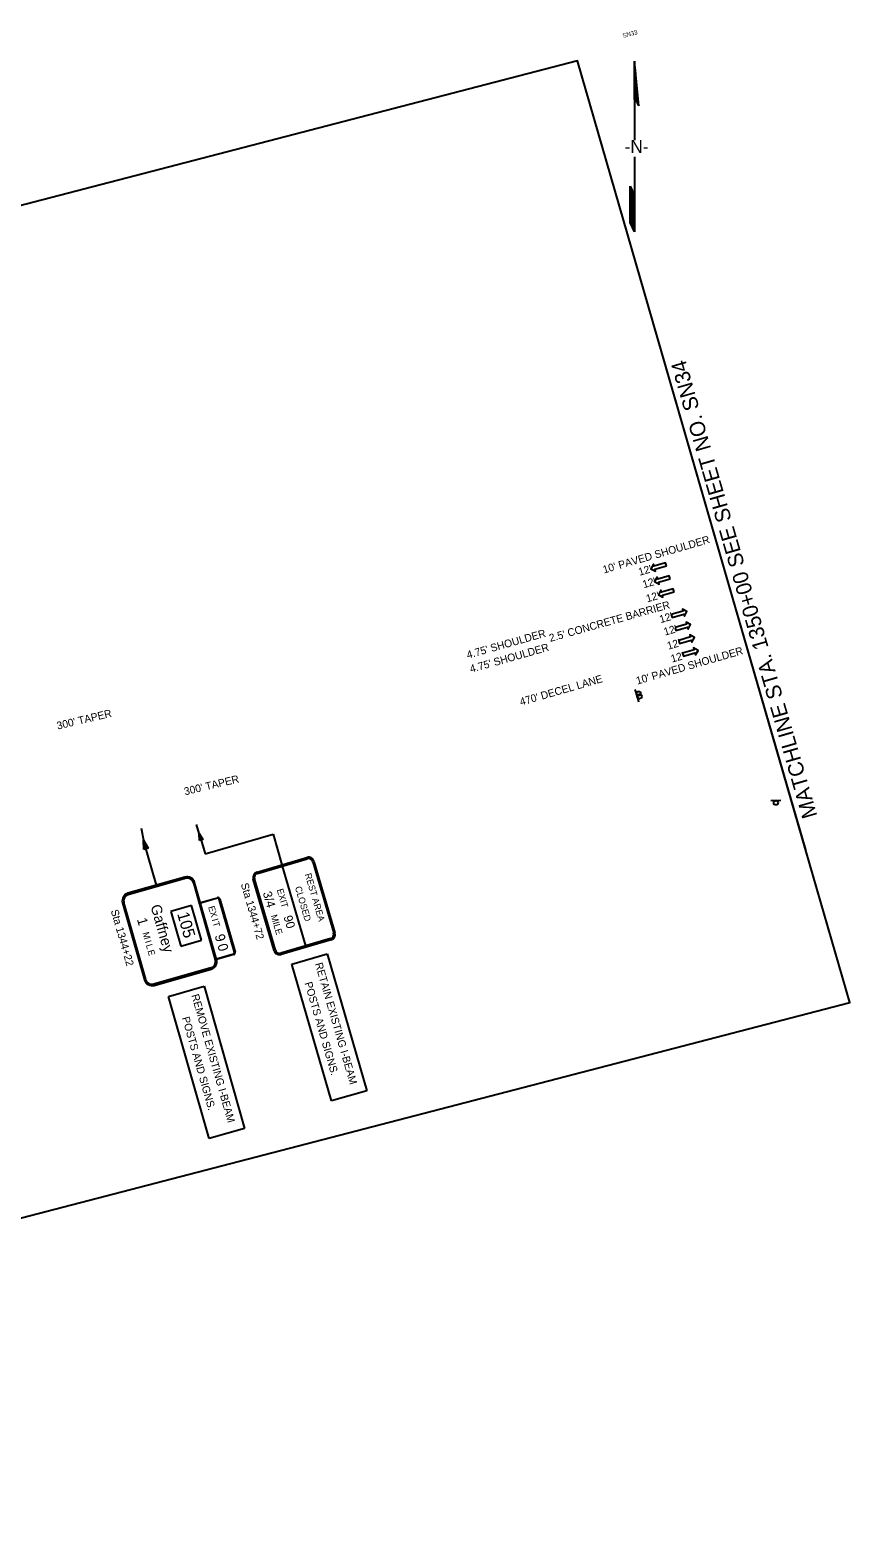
# Model space of a CAD drawing. Extents: x 1782675 to 1784334, y 1180551 to 1181928.
# Drawn here: x 1783586 to 1784334, y 1180551 to 1181928 of the extents above; entities that cross this region are included whole.
import ezdxf

# ---------------------------------------------------------------- set-up
doc = ezdxf.new("R2010")
doc.units = 0
for name, color, linetype in [('RD_HC_Data', 7, 'Continuous'), ('RD_PD_GR', 7, 'Continuous'), ('RD_PD_MedBWall', 7, 'Continuous'), ('RD_PD_PatLn1', 7, 'Continuous'), ('RD_PD_PaveShd', 7, 'Continuous'), ('RD_SHT_MatchLine', 7, 'Continuous'), ('RD_Sketch1', 7, 'Continuous')]:
    doc.layers.add(name, color=color, linetype=linetype)

# ---------------------------------------------------------------- blocks, each defined once
blk = doc.blocks.new('NA5')
at = {"layer": 'RD_Sketch1'}
for p, q in [((47.5, 65.9), (26.8, 37.4)), ((26.8, 30.6), (47.5, 65.9)), ((27.2, 37.5), (14.5, 19.8)), ((28.1, 38.3), (26.8, 30.6)), ((14.5, 19.8), (5.5, 7.2)), ((-3.5, -5.3), (-18.5, -26.3)), ((-18.5, -26.3), (-43.3, -60.9)), ((-30.6, -36.2), (-22.3, -24.7)), ((-22.3, -24.7), (-24, -34)), ((-41.6, -51.6), (-30.6, -36.2)), ((-43.3, -60.9), (-41.6, -51.6))]:
    blk.add_line(p, q, dxfattribs=at)
for points in [[(27.4, 37.8), (47.4, 65.8)], [(27.6, 37.9), (46.9, 64.9)], [(27.8, 38.1), (46.4, 64)], [(27.8, 36.8), (42.2, 56.8)], [(27.8, 36.6), (41.7, 56)], [(27.9, 37.4), (43.8, 59.5)], [(27.9, 37.2), (43.2, 58.6)], [(27.9, 37), (42.7, 57.7)], [(28, 38.1), (45.3, 62.2)], [(28, 37.9), (44.8, 61.3)], [(28, 37.7), (44.3, 60.4)], [(28.1, 38.3), (45.8, 63.1)], [(26.9, 37.5), (29.9, 41.7)], [(27.1, 37.6), (39.2, 54.5)], [(27.2, 33.2), (33.3, 41.6)], [(27.3, 33.9), (34.8, 44.3)], [(27.3, 33.7), (34.3, 43.4)], [(27.3, 33.4), (33.8, 42.5)], [(27.4, 34.5), (36.4, 47)], [(27.4, 34.3), (35.9, 46.1)], [(27.4, 34.1), (35.4, 45.2)], [(27.5, 34.9), (37.5, 48.8)], [(27.5, 34.7), (36.9, 47.9)], [(27.6, 35.5), (39, 51.5)], [(27.6, 35.3), (38.5, 50.6)], [(27.6, 35.1), (38, 49.7)], [(27.7, 36.2), (40.6, 54.2)], [(27.7, 36), (40.1, 53.3)], [(27.7, 35.8), (39.6, 52.4)], [(27.8, 36.4), (41.1, 55.1)], [(26.8, 30.7), (27, 30.9)], [(26.9, 31.3), (28.5, 33.6)], [(26.9, 31.1), (28, 32.7)], [(26.9, 30.9), (27.5, 31.8)], [(27, 32), (30.1, 36.3)], [(27, 31.8), (29.6, 35.4)], [(27, 31.5), (29.1, 34.5)], [(27.1, 32.6), (31.7, 39)], [(27.1, 32.4), (31.2, 38.1)], [(27.1, 32.2), (30.6, 37.2)], [(27.2, 33), (32.7, 40.7)], [(27.2, 32.8), (32.2, 39.9)], [(-42.1, -54.4), (-22.8, -27.5)], [(-42, -53.7), (-22.7, -26.8)], [(-42, -53.9), (-22.7, -27.1)], [(-42, -54.2), (-22.8, -27.3)], [(-41.9, -53.3), (-22.6, -26.4)], [(-41.9, -53.5), (-22.7, -26.6)], [(-41.8, -52.6), (-22.5, -25.7)], [(-41.8, -52.8), (-22.5, -26)], [(-41.8, -53.1), (-22.6, -26.2)], [(-41.7, -52.2), (-22.4, -25.3)], [(-41.7, -52.4), (-22.5, -25.5)], [(-41.6, -51.7), (-22.3, -24.9)], [(-41.6, -52), (-22.4, -25.1)], [(-43.3, -60.8), (-24, -33.9)], [(-43.2, -60.1), (-23.9, -33.2)], [(-43.2, -60.3), (-23.9, -33.4)], [(-43.2, -60.5), (-24, -33.6)], [(-43.1, -59.7), (-23.8, -32.8)], [(-43.1, -59.9), (-23.9, -33)], [(-43, -59), (-23.7, -32.1)], [(-43, -59.2), (-23.7, -32.3)], [(-43, -59.4), (-23.8, -32.5)], [(-42.9, -58.6), (-23.6, -31.7)], [(-42.9, -58.8), (-23.7, -31.9)], [(-42.8, -58.1), (-23.5, -31.2)], [(-42.8, -58.3), (-23.6, -31.4)], [(-42.7, -57.5), (-23.4, -30.6)], [(-42.7, -57.7), (-23.5, -30.8)], [(-42.7, -57.9), (-23.5, -31)], [(-42.6, -57), (-23.3, -30.1)], [(-42.6, -57.2), (-23.4, -30.4)], [(-42.5, -56.4), (-23.2, -29.5)], [(-42.5, -56.6), (-23.2, -29.7)], [(-42.5, -56.8), (-23.3, -29.9)], [(-42.4, -55.9), (-23.1, -29)], [(-42.4, -56.1), (-23.2, -29.3)], [(-42.3, -55.3), (-23, -28.4)], [(-42.3, -55.5), (-23, -28.6)], [(-42.3, -55.7), (-23.1, -28.8)], [(-42.2, -54.8), (-22.9, -27.9)], [(-42.2, -55), (-23, -28.2)], [(-42.1, -54.6), (-22.9, -27.7)]]:
    blk.add_lwpolyline(points, dxfattribs=at)
blk.add_text('-N-', height=11.81, rotation=324.3865, dxfattribs=at).set_placement((-8.8, 3))
blk = doc.blocks.new('SARRW2')
at = {"layer": 'RD_PD_GR'}
blk.add_lwpolyline([(-12, 1.2), (-12, -1.2), (-2.8, -1.2), (-2.8, -2.8), (0, 0), (-2.8, 2.8), (-2.8, 1.2)], close=True, dxfattribs=at)

msp = doc.modelspace()

# ---------------------------------------------------------------- linework, layer by layer
at = {"layer": 'RD_HC_Data'}
msp.add_lwpolyline([(1784230.2, 1181398.9), (1784085.2, 1181900.3), (1784085.2, 1181900.3), (1782674.8, 1181533.5), (1782822.1, 1180797.2), (1782871.2, 1180551.3), (1783573.5, 1180734), (1783547.1, 1180835.6), (1784333.9, 1181040.2)], close=True, dxfattribs=at)
at = {"layer": 'RD_PD_PatLn1'}
for p, q in [((1784137.8, 1181326.1), (1784140.5, 1181317.5)), ((1784137.8, 1181326.1), (1784140.5, 1181317.5)), ((1784138.9, 1181323.6), (1784141, 1181314.9)), ((1784138.9, 1181323.6), (1784141, 1181314.9)), ((1784270.8, 1181224.8), (1784261.8, 1181224.3)), ((1783686.9, 1181199.4), (1783689.2, 1181188.6)), ((1783740.1, 1181194.6), (1783737.6, 1181202.7)), ((1783740.1, 1181194.6), (1783745.4, 1181176)), ((1783745.4, 1181176), (1783807.4, 1181194)), ((1783807.4, 1181194), (1783815.5, 1181166)), ((1783701, 1181147.4), (1783689.2, 1181188.6)), ((1783844.7, 1181169.1), (1783863.9, 1181103.9)), ((1783824.6, 1181075.2), (1783856.9, 1181084.6)), ((1783856.9, 1181084.6), (1783893, 1180959.6)), ((1783860.8, 1180950.3), (1783824.6, 1181075.2)), ((1783712.1, 1181045.8), (1783744.4, 1181055)), ((1783744.4, 1181055), (1783781.4, 1180925.2)), ((1783749.1, 1180915.9), (1783712.1, 1181045.8)), ((1783893, 1180959.6), (1783860.8, 1180950.3)), ((1783781.4, 1180925.2), (1783749.1, 1180915.9))]:
    msp.add_line(p, q, dxfattribs=at)
for points in [[(1783740.3, 1181188.2), (1783740.1, 1181194.6), (1783743.2, 1181189.1)], [(1783689.5, 1181180.1), (1783689.2, 1181188.6), (1783693.4, 1181181.3)]]:
    msp.add_lwpolyline(points, close=True, dxfattribs=at)
for points in [[(1783792.8, 1181159.3), (1783838.3, 1181172.7)], [(1783793.1, 1181158.1), (1783838.6, 1181171.5)], [(1783837.3, 1181091.9), (1783815.9, 1181164.8)], [(1783843.6, 1181168.8), (1783862.8, 1181103.6)], [(1783726.9, 1181154.8), (1783675, 1181140)], [(1783675.3, 1181138.8), (1783727.3, 1181153.7)], [(1783808.4, 1181087.6), (1783789.3, 1181152.8)], [(1783809.6, 1181087.9), (1783790.4, 1181153.2)], [(1783734.7, 1181149.5), (1783754.7, 1181079.2)], [(1783755.9, 1181079.6), (1783735.8, 1181149.9)], [(1783670.1, 1181131.1), (1783690.1, 1181060.8)], [(1783691.3, 1181061.1), (1783671.2, 1181131.4)], [(1783733.1, 1181128.8), (1783714.2, 1181123.4)], [(1783714.2, 1181123.4), (1783723.2, 1181091.6)], [(1783742.2, 1181097), (1783733.1, 1181128.8)], [(1783756.8, 1181135.4), (1783741.2, 1181130.9), (1783741.1, 1181131.5), (1783756.7, 1181135.9)], [(1783772.1, 1181086.1), (1783758.3, 1181134.5)], [(1783758.9, 1181134.7), (1783772.7, 1181086.2)], [(1783723.2, 1181091.6), (1783742.2, 1181097)], [(1783860, 1181098.6), (1783814.5, 1181085.2)], [(1783860.4, 1181097.4), (1783814.9, 1181084.1)], [(1783755.7, 1181080.1), (1783771.3, 1181084.6)], [(1783771.5, 1181084), (1783755.9, 1181079.6), (1783755.7, 1181080.1)], [(1783750.6, 1181071.8), (1783698.7, 1181057)], [(1783699, 1181055.8), (1783750.9, 1181070.7)]]:
    msp.add_lwpolyline(points, dxfattribs=at)
for centre in [(1784141.1, 1181322.4), (1784141.1, 1181322.4), (1784141.9, 1181319.7), (1784141.9, 1181319.7), (1784266.4, 1181222.6)]:
    msp.add_circle(centre, 2, dxfattribs=at)
for centre, radius, start, end in [((1783839.8, 1181167.7), 5.2, 16.3721, 106.3721), ((1783839.8, 1181167.7), 4, 16.3721, 106.3721), ((1783728.9, 1181147.9), 7.2, 15.921, 105.921), ((1783728.9, 1181147.9), 6, 15.921, 105.921), ((1783794.3, 1181154.3), 5.2, 106.3721, 196.3721), ((1783794.3, 1181154.3), 4, 106.3721, 196.3721), ((1783677, 1181133.1), 7.2, 105.921, 195.921), ((1783677, 1181133.1), 6, 105.921, 195.921), ((1783757.1, 1181134.2), 1.8, 15.921, 105.921), ((1783757.1, 1181134.2), 1.2, 15.921, 105.921), ((1783858.9, 1181102.4), 4, 286.3721, 16.3721), ((1783858.9, 1181102.4), 5.2, 286.3721, 16.3721), ((1783771, 1181085.7), 1.2, 285.921, 15.921), ((1783771, 1181085.7), 1.8, 285.921, 15.921), ((1783813.4, 1181089.1), 5.2, 196.3721, 286.3721), ((1783813.4, 1181089.1), 4, 196.3721, 286.3721), ((1783749, 1181077.6), 6, 285.921, 15.921), ((1783749, 1181077.6), 7.2, 285.921, 15.921), ((1783697, 1181062.8), 7.2, 195.921, 285.921), ((1783697, 1181062.8), 6, 195.921, 285.921)]:
    msp.add_arc(centre, radius, start, end, dxfattribs=at)
at = {"layer": 'RD_SHT_MatchLine'}
msp.add_lwpolyline([(1784293.6, 1181179.7), (1784224.1, 1181419.8), (1784154.7, 1181660)], dxfattribs=at)

# ---------------------------------------------------------------- block references
at = {"layer": 'RD_PD_GR', "yscale": 1.2000000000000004}
for p, xscale, rotation in [((1784152.3, 1181436.4), 1.2000000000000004, -163.87257597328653), ((1784155.7, 1181424.6), 1.2000000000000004, -163.87257597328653), ((1784159.2, 1181412.6), 1.2000000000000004, -163.87257597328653), ((1784185.2, 1181397.3), 1.2000000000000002, 16.12742402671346), ((1784188.6, 1181385.3), 1.2000000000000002, 16.12742402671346), ((1784192, 1181373.6), 1.2000000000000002, 16.12742402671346), ((1784195.4, 1181361.8), 1.2000000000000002, 16.12742402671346)]:
    msp.add_blockref('SARRW2', p, dxfattribs=dict(at, xscale=xscale, rotation=rotation))
at = {"layer": 'RD_SHT_MatchLine', "rotation": 35.61349782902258}
msp.add_blockref('NA5', (1784137.2, 1181818.8), dxfattribs=at)

# ---------------------------------------------------------------- texts
at = {"layer": 'RD_PD_MedBWall'}
for s, rotation, p in [("10' PAVED SHOULDER", 16.1274, (1784109.5, 1181432)), ("12'", 16.1274, (1784142, 1181429.9)), ("12'", 16.1274, (1784145.8, 1181418.5)), ("12'", 16.1274, (1784149, 1181405.6)), ("2.5' CONCRETE BARRIER", 15.7275, (1784060.5, 1181369.5)), ("12'", 16.1274, (1784161.2, 1181386.6)), ("12'", 16.1274, (1784165.1, 1181375.2)), ("4.75' SHOULDER", 15.8603, (1783985.2, 1181354.1)), ("12'", 16.1274, (1784168.2, 1181362.4)), ("4.75' SHOULDER", 15.8603, (1783988.1, 1181341.3)), ("10' PAVED SHOULDER", 16.1274, (1784139.9, 1181330.5)), ("12'", 16.1274, (1784171.6, 1181350.6)), ("470' DECEL LANE", 16.1276, (1784033.7, 1181311.2)), ("300' TAPER", 13.4377, (1783610.9, 1181289.4)), ("300' TAPER", 13.4377, (1783727.1, 1181229.4))]:
    msp.add_text(s, height=7, rotation=rotation, dxfattribs=at).set_placement(p)
at = {"layer": 'RD_PD_PatLn1'}
for s, height, rotation, p in [('REST AREA', 6, 286.3721, (1783836.3, 1181157.3)), ('Sta 1344+72', 7, 286.1277, (1783777.9, 1181148.3)), ('3/4', 8, 286.3721, (1783798, 1181140.4)), ('EXIT', 6, 286.3721, (1783810.7, 1181143.2)), ('CLOSED', 6, 286.3721, (1783827.3, 1181145.4)), ('Sta 1344+22', 7, 285.9211, (1783659.2, 1181124.1)), ('Gaffney', 9.6, 285.921, (1783695.5, 1181128.2)), ('E', 6, 285.921, (1783748.1, 1181127.5)), ('X', 6, 285.921, (1783749.5, 1181122.6)), ('1', 9, 285.921, (1783683.1, 1181116.2)), ('105', 10.8, 285.921, (1783719.8, 1181121.3)), ('I', 6, 285.921, (1783751.4, 1181116)), ('T', 6, 285.921, (1783752.2, 1181113.2)), ('MILE', 6, 286.3721, (1783805.2, 1181119.5)), ('90', 8, 286.3721, (1783816.9, 1181118.5)), ('M', 6, 285.921, (1783688.2, 1181103.7)), ('I', 6, 285.921, (1783690.3, 1181096.1)), ('9', 9, 285.921, (1783754, 1181101.3)), ('L', 6, 285.921, (1783691.3, 1181092.7)), ('E', 6, 285.921, (1783692.8, 1181087.4)), ('0', 9, 285.921, (1783756.5, 1181092.6)), ('RETAIN EXISTING I-BEAM', 7, 286.1277, (1783845.6, 1181075.6)), ('POSTS AND SIGNS.', 7, 286.1277, (1783836.1, 1181058)), ('REMOVE EXISTING I-BEAM', 7, 285.9211, (1783732.8, 1181046.8)), ('POSTS AND SIGNS.', 7, 285.9211, (1783724.2, 1181026.2))]:
    msp.add_text(s, height=height, rotation=rotation, dxfattribs=at).set_placement(p)
at = {"layer": 'RD_PD_PaveShd'}
msp.add_text('SN33', height=4, rotation=14.5806, dxfattribs=at).set_placement((1784127, 1181921.2))
at = {"layer": 'RD_SHT_MatchLine'}
msp.add_text('MATCHLINE STA. 1350+00 SEE SHEET NO. SN34', height=14, rotation=106.1276, dxfattribs=at).set_placement((1784304.4, 1181210.7))

doc.saveas('drawing.dxf')
